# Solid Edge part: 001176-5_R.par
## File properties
Last saved by: morva
Revision: 82
Accuracy: 0.990
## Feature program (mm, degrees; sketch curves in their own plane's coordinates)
body "unnamed Body 1"
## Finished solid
Body 1: solid body, 44 faces, 88 edges, 47 vertices.
  Faces by surface: cylinder 18, plane 14, spline 4, cone 2, spun 2, swept 2, torus 2
  Edges by curve: curve on surface 32, line 31, circle 23, spline 2
Bounding box of the edges (mm; curved faces can reach further): 11.106 x 10.410 x 19.179, from (409.2, 381.9451, 153.252) to (420.3064, 392.3553, 172.4307).
Cylindrical faces by radius (mm): R0.4 x5, R0.4491 x2, R0.4493 x4, R0.4507 x2, R2 x2, R3.5 x3
Conical faces (half-angle, radius in mm at the cone's reference point): 45 deg R2 x2
Toroidal faces (ring radius, tube radius in mm): R2 r1.5 x2
Planar faces by outward normal: oblique 14
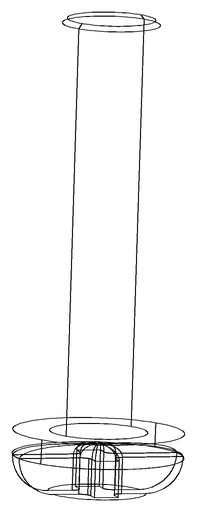
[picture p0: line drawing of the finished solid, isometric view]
